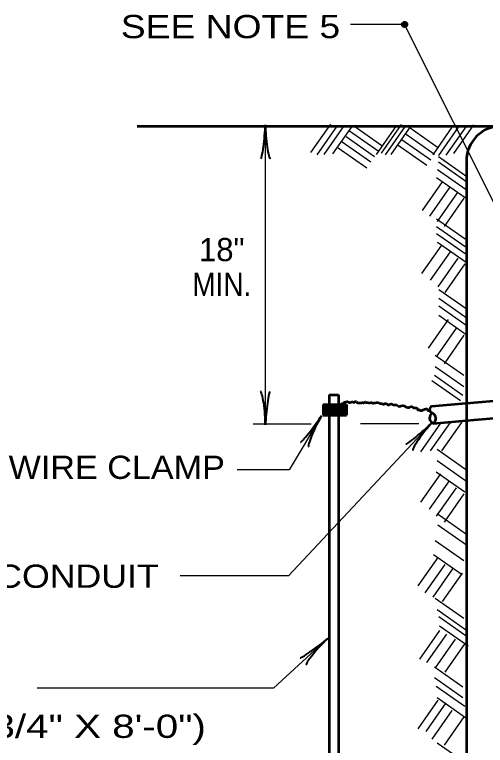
# Model space of a CAD drawing. Extents: x -560 to 120, y 26 to 466.
# Drawn here: x -192.3 to -151.7, y 113.4 to 176.3 of the extents above; entities that cross this region are included whole.
import ezdxf
from ezdxf.enums import TextEntityAlignment as Align

# ---------------------------------------------------------------- set-up
doc = ezdxf.new("R2010")
doc.units = 0
doc.header["$LTSCALE"] = 0.8
doc.header["$PDMODE"] = 32
doc.header["$PDSIZE"] = 0.4
doc.linetypes.add('LONG_DASHED', pattern=[7.5, 6, -1.5])
doc.layers.add('1', color=7, linetype='Continuous', lineweight=53)

msp = doc.modelspace()

# ---------------------------------------------------------------- linework, layer by layer
at = {"layer": '1', "lineweight": 25}
for p, q in [((-158.6532, 175.4604), (-163.3054, 175.4604)), ((-147.0989, 152.3519), (-158.6532, 175.4604)), ((-166.7455, 164.4171), (-165.0248, 166.8745)), ((-160.6313, 164.3796), (-158.9107, 166.837)), ((-170.6512, 140.9738), (-170.6512, 166.7859)), ((-166.1829, 164.2296), (-164.4622, 166.687)), ((-165.5828, 164.2671), (-163.8621, 166.7245)), ((-164.8326, 164.3047), (-163.1119, 166.7621)), ((-163.3972, 166.2917), (-160.9398, 164.571)), ((-163.0597, 166.7417), (-160.6022, 165.0211)), ((-161.0815, 164.2671), (-159.3608, 166.7245)), ((-160.2937, 164.2296), (-158.5731, 166.687)), ((-159.8061, 164.2671), (-158.0854, 166.7245)), ((-158.1832, 166.5542), (-155.7258, 164.8335)), ((-156.2052, 164.2296), (-154.4845, 166.687)), ((-155.7175, 164.1545), (-153.9968, 166.6119)), ((-155.0798, 164.1921), (-153.3592, 166.6495)), ((-154.4047, 164.3421), (-152.684, 166.7995)), ((-163.6973, 165.804), (-161.2398, 164.0833)), ((-158.5208, 165.9915), (-156.0633, 164.2708)), ((-164.0349, 165.3539), (-161.5774, 163.6333)), ((-159.196, 165.0538), (-156.7385, 163.3331)), ((-158.8584, 165.5039), (-156.4009, 163.7832)), ((-164.3725, 164.8287), (-161.915, 163.1081)), ((-155.7451, 164.0785), (-153.2876, 162.3578)), ((-155.7451, 163.6284), (-153.2876, 161.9077)), ((-155.8201, 162.9532), (-153.3626, 161.2325)), ((-157.1053, 159.4282), (-155.3847, 161.8857)), ((-155.8951, 162.278), (-153.4376, 160.5573)), ((-156.4677, 158.9407), (-154.747, 161.3981)), ((-155.83, 158.4905), (-154.1093, 160.9479)), ((-155.2298, 158.0404), (-153.5092, 160.4978)), ((-155.8951, 158.7146), (-153.4376, 156.9939)), ((-155.8951, 158.0394), (-153.4376, 156.3187)), ((-155.8951, 157.4392), (-153.4376, 155.7186)), ((-157.1804, 153.9892), (-155.4597, 156.4467)), ((-155.8201, 156.689), (-153.3626, 154.9683)), ((-156.4302, 153.4266), (-154.7095, 155.884)), ((-155.755, 152.8639), (-154.0343, 155.3213)), ((-155.1548, 152.3762), (-153.4342, 154.8337)), ((-155.7076, 152.6379), (-153.2501, 150.9172)), ((-155.7076, 151.8877), (-153.2501, 150.167)), ((-155.7076, 151.2125), (-153.2501, 149.4918)), ((-156.5803, 147.5749), (-154.8596, 150.0323)), ((-155.7076, 150.4247), (-153.2501, 148.7041)), ((-155.9051, 146.8247), (-154.1844, 149.2822)), ((-155.2298, 146.2246), (-153.5092, 148.682)), ((-156.0077, 146.9738), (-153.5502, 145.2532)), ((-156.0077, 145.9986), (-153.5502, 144.2779)), ((-156.3077, 144.7982), (-153.8502, 143.0776)), ((-156.0827, 145.2484), (-153.6252, 143.5277)), ((-171.7057, 141.0415), (-166.7057, 141.0415)), ((-162.4412, 141.079), (-157.4412, 141.079)), ((-157.2554, 138.6475), (-155.5348, 141.1049)), ((-156.4302, 138.7225), (-154.7095, 141.1799)), ((-155.4549, 138.7225), (-153.7343, 141.1799)), ((-155.8576, 138.8716), (-153.4001, 137.1509)), ((-155.8576, 137.8963), (-153.4001, 136.1757)), ((-157.2554, 134.2962), (-155.5348, 136.7537)), ((-155.9327, 136.9211), (-153.4752, 135.2004)), ((-156.5052, 133.6961), (-154.7845, 136.1535)), ((-155.905, 133.0959), (-154.1843, 135.5533)), ((-155.2298, 132.5708), (-153.5092, 135.0282)), ((-155.8577, 133.32), (-153.4002, 131.5993)), ((-155.7826, 132.3448), (-153.3251, 130.6241)), ((-156.0077, 130.9943), (-153.5502, 129.2737)), ((-156.1577, 129.794), (-153.7002, 128.0733)), ((-157.4805, 127.0943), (-155.7598, 129.5517)), ((-156.8803, 126.4941), (-155.1597, 128.9515)), ((-156.2052, 126.119), (-154.4845, 128.5764)), ((-155.3799, 125.7439), (-153.6592, 128.2013)), ((-156.0077, 126.0431), (-153.5502, 124.3224)), ((-155.8576, 125.0677), (-153.4001, 123.3471)), ((-155.7076, 124.4676), (-153.2501, 122.7469)), ((-155.6325, 123.6424), (-153.175, 121.9218)), ((-157.3305, 120.7926), (-155.6098, 123.25)), ((-156.7303, 120.4925), (-155.0097, 122.9499)), ((-155.9801, 120.0423), (-154.2594, 122.4997)), ((-155.1549, 119.6672), (-153.4342, 122.1247)), ((-156.0828, 120.1163), (-153.6252, 118.3957)), ((-156.0828, 119.2161), (-153.6252, 117.4954)), ((-155.9327, 118.4659), (-153.4752, 116.7452)), ((-157.4805, 114.7909), (-155.7598, 117.2483)), ((-155.8577, 117.4906), (-153.4002, 115.7699)), ((-156.8053, 114.5658), (-155.0847, 117.0232)), ((-156.2802, 113.8907), (-154.5595, 116.3481)), ((-155.2299, 113.3655), (-153.5093, 115.8229)), ((-155.8577, 113.5896), (-153.4002, 111.8689))]:
    msp.add_line(p, q, dxfattribs=at)
at = {"layer": '1'}
for p, q in [((-181.6935, 166.6995), (-147.5832, 166.6995)), ((-165.1448, 143.5618), (-164.3448, 143.5618)), ((-165.1448, 143.5618), (-165.1448, 142.791)), ((-164.3448, 143.543), (-164.3448, 143.2187)), ((-164.3448, 143.543), (-164.3448, 142.791)), ((-165.6699, 142.7062), (-163.6699, 142.7062)), ((-165.6699, 142.7062), (-165.6699, 141.8061)), ((-165.6325, 142.7062), (-165.6325, 141.8061)), ((-165.6232, 142.7062), (-165.6232, 141.8061)), ((-165.6044, 142.7062), (-165.6044, 141.8061)), ((-165.5857, 142.7062), (-165.5857, 141.8061)), ((-165.5575, 142.7062), (-165.5575, 141.8061)), ((-165.5107, 142.7062), (-165.5107, 141.8061)), ((-165.4638, 142.7062), (-165.4638, 141.8061)), ((-165.4169, 142.7062), (-165.4169, 141.8061)), ((-165.3981, 142.7062), (-165.3981, 141.8061)), ((-165.3606, 142.7062), (-165.3606, 141.8061)), ((-165.3512, 142.7062), (-165.3512, 141.8061)), ((-165.3231, 142.7062), (-165.3231, 141.8061)), ((-165.295, 142.7062), (-165.295, 141.8061)), ((-165.295, 142.7062), (-165.295, 141.8061)), ((-165.2856, 142.7062), (-165.2856, 141.8061)), ((-165.2763, 142.7062), (-165.2763, 141.8061)), ((-165.2481, 142.7062), (-165.2481, 141.8061)), ((-165.2293, 142.7062), (-165.2293, 141.8061)), ((-165.22, 142.7062), (-165.22, 141.8061)), ((-165.1918, 142.7062), (-165.1918, 141.8061)), ((-165.1918, 142.7062), (-165.1918, 141.8061)), ((-165.1825, 142.7062), (-165.1825, 141.8061)), ((-165.1543, 142.7062), (-165.1543, 141.8061)), ((-165.1448, 142.8247), (-165.1448, 140.4947)), ((-165.1262, 142.7062), (-165.1262, 141.8061)), ((-165.1262, 142.7062), (-165.1262, 141.8061)), ((-165.0888, 142.7062), (-165.0888, 141.8061)), ((-165.0888, 142.7062), (-165.0888, 141.8061)), ((-165.0699, 142.7062), (-165.0699, 141.8061)), ((-165.0698, 142.7056), (-165.0698, 142.3453)), ((-165.0324, 142.7062), (-165.0324, 141.8061)), ((-165.0324, 142.7062), (-165.0324, 141.8061)), ((-165.0043, 142.7062), (-165.0043, 141.8061)), ((-164.9856, 142.7062), (-164.9856, 141.8061)), ((-164.9668, 142.7062), (-164.9668, 141.8061)), ((-164.9387, 142.7062), (-164.9387, 141.8061)), ((-164.9199, 142.7062), (-164.9199, 141.8061)), ((-164.8918, 142.7062), (-164.8918, 141.8061)), ((-164.8637, 142.7062), (-164.8637, 141.8061)), ((-164.8543, 142.7062), (-164.8543, 141.8061)), ((-164.8449, 142.7062), (-164.8449, 141.8061)), ((-164.8262, 142.7062), (-164.8262, 141.8061)), ((-164.8074, 142.7062), (-164.8074, 141.8061)), ((-164.7981, 142.7062), (-164.7981, 141.8061)), ((-164.7793, 142.7062), (-164.7793, 141.8061)), ((-164.7699, 142.7062), (-164.7699, 141.8061)), ((-164.7606, 142.7062), (-164.7606, 141.8061)), ((-164.7417, 142.7062), (-164.7417, 141.8061)), ((-164.7417, 142.7062), (-164.7417, 141.8061)), ((-164.7417, 142.7062), (-164.7417, 141.8061)), ((-164.7137, 142.7062), (-164.7137, 141.8061)), ((-164.7137, 142.7062), (-164.7137, 141.8061)), ((-164.6855, 142.7062), (-164.6855, 141.8061)), ((-164.6855, 142.7062), (-164.6855, 141.8061)), ((-164.6762, 142.7062), (-164.6762, 141.8061)), ((-164.6574, 142.7062), (-164.6574, 141.8061)), ((-164.6199, 142.7062), (-164.6199, 141.8061)), ((-164.6105, 142.7062), (-164.6105, 141.8061)), ((-164.6105, 142.7062), (-164.6105, 141.8061)), ((-164.5917, 142.7062), (-164.5917, 141.8061)), ((-164.5637, 142.7062), (-164.5637, 141.8061)), ((-164.5542, 142.7062), (-164.5542, 141.8061)), ((-164.5449, 142.7062), (-164.5449, 141.8061)), ((-164.5355, 142.7062), (-164.5355, 141.8061)), ((-164.5262, 142.7062), (-164.5262, 141.8061)), ((-164.498, 142.7062), (-164.498, 141.8061)), ((-164.4793, 142.7062), (-164.4793, 141.8061)), ((-164.4699, 142.7062), (-164.4699, 141.8061)), ((-164.4512, 142.7062), (-164.4512, 141.8061)), ((-164.423, 142.7062), (-164.423, 141.8061)), ((-164.4042, 142.7062), (-164.4042, 141.8061)), ((-164.4042, 142.7062), (-164.4042, 141.8061)), ((-164.3948, 142.7062), (-164.3948, 141.8061)), ((-164.3855, 142.7062), (-164.3855, 141.8061)), ((-164.3667, 142.7062), (-164.3667, 141.8061)), ((-164.3667, 142.7062), (-164.3667, 141.8061)), ((-164.3573, 142.7062), (-164.3573, 141.8061)), ((-164.3448, 142.8342), (-164.3448, 140.5323)), ((-164.3386, 142.7062), (-164.3386, 141.8061)), ((-164.3386, 142.7062), (-164.3386, 141.8061)), ((-164.3293, 142.7062), (-164.3293, 141.8061)), ((-164.3105, 142.7062), (-164.3105, 141.8061)), ((-164.2918, 142.7062), (-164.2918, 141.8061)), ((-164.2823, 142.7062), (-164.2823, 141.8061)), ((-164.2698, 142.7051), (-164.2698, 142.3453)), ((-164.2636, 142.7062), (-164.2636, 141.8061)), ((-164.2542, 142.7062), (-164.2542, 141.8061)), ((-164.2448, 142.7062), (-164.2448, 141.8061)), ((-164.2167, 142.7062), (-164.2167, 141.8061)), ((-164.1886, 142.7062), (-164.1886, 141.8061)), ((-164.1792, 142.7062), (-164.1792, 141.8061)), ((-164.1698, 142.7062), (-164.1698, 141.8061)), ((-164.1511, 142.7062), (-164.1511, 141.8061)), ((-164.1418, 142.7062), (-164.1418, 141.8061)), ((-164.1323, 142.7062), (-164.1323, 141.8061)), ((-164.1043, 142.7062), (-164.1043, 141.8061)), ((-164.0667, 142.7062), (-164.0667, 141.8061)), ((-164.0573, 142.7062), (-164.0573, 141.8061)), ((-164.0573, 142.7062), (-164.0573, 141.8061)), ((-164.0573, 142.7062), (-164.0573, 141.8061)), ((-164.0479, 142.7062), (-164.0479, 141.8061)), ((-164.0198, 142.7062), (-164.0198, 141.8061)), ((-164.0198, 142.7062), (-164.0198, 141.8061)), ((-164.0104, 142.7062), (-164.0104, 141.8061)), ((-164.0011, 142.7062), (-164.0011, 141.8061)), ((-163.9823, 142.7062), (-163.9823, 141.8061)), ((-163.9729, 142.7062), (-163.9729, 141.8061)), ((-163.9636, 142.7062), (-163.9636, 141.8061)), ((-163.9448, 142.7062), (-163.9448, 141.8061)), ((-163.9261, 142.7062), (-163.9261, 141.8061)), ((-163.9167, 142.7062), (-163.9167, 141.8061)), ((-163.9073, 142.7062), (-163.9073, 141.8061)), ((-163.9073, 142.7062), (-163.9073, 141.8061)), ((-163.8792, 142.7062), (-163.8792, 141.8061)), ((-163.8604, 142.7062), (-163.8604, 141.8061)), ((-163.8604, 142.7062), (-163.8604, 141.8061)), ((-163.8511, 142.7062), (-163.8511, 141.8061)), ((-163.8511, 142.7062), (-163.8511, 141.8061)), ((-163.8229, 142.7062), (-163.8229, 141.8061)), ((-163.8136, 142.7062), (-163.8136, 141.8061)), ((-163.8136, 142.7062), (-163.8136, 141.8061)), ((-163.7948, 142.7062), (-163.7948, 141.8061)), ((-163.7948, 142.7062), (-163.7948, 141.8061)), ((-163.7948, 142.7062), (-163.7948, 141.8061)), ((-163.7854, 142.7062), (-163.7854, 141.8061)), ((-163.7854, 142.7062), (-163.7854, 141.8061)), ((-163.7479, 142.7062), (-163.7479, 141.8061)), ((-163.7385, 142.7062), (-163.7385, 141.8061)), ((-163.7292, 142.7062), (-163.7292, 141.8061)), ((-163.7104, 142.7062), (-163.7104, 141.8061)), ((-163.7104, 142.7062), (-163.7104, 141.8061)), ((-163.701, 142.7062), (-163.701, 141.8061)), ((-163.701, 142.7062), (-163.701, 141.8061)), ((-163.6729, 142.7062), (-163.6729, 141.8061)), ((-163.6699, 142.7062), (-163.6699, 141.8061)), ((-156.3286, 142.5751), (-153.34, 142.8366)), ((-165.6699, 141.8061), (-163.6699, 141.8061)), ((-156.1978, 141.0808), (-153.3261, 141.3321)), ((-165.1448, 140.7231), (-165.1448, 83.0187)), ((-164.3448, 140.7231), (-164.3448, 83.0187))]:
    msp.add_line(p, q, dxfattribs=at)
at = {"layer": '1', "linetype": 'LONG_DASHED'}
for p, q in [((-153.3254, 142.8416), (-143.2353, 143.7244)), ((-153.3254, 141.3358), (-142.6482, 142.27))]:
    msp.add_line(p, q, dxfattribs=at)
at = {"layer": '1'}
msp.add_lwpolyline([(-153.3254, 163.6995), (-153.3254, 93.7352), (-116.1271, 93.7352)], dxfattribs=at)
at = {"layer": '1', "lineweight": 25}
for points in [[(-165.8134, 141.7572), (-168.5892, 137.1059), (-173.096, 137.1059)], [(-156.2858, 141.157), (-168.6642, 127.9534), (-177.9922, 127.9534)], [(-165.2883, 122.5519), (-169.9395, 118.2757), (-190.3148, 118.2757)]]:
    msp.add_lwpolyline(points, dxfattribs=at)
at = {"layer": '1'}
for centre, radius, start, end in [((-150.3254, 163.6995), 3, 90, 180), ((-155.9689, 141.5592), 0.5304, 124.39884, 244.42408)]:
    msp.add_arc(centre, radius, start, end, dxfattribs=at)
at = {"layer": '1', "lineweight": 25}
msp.add_arc((-150.3254, 163.6995), 3, 90, 180, dxfattribs=at)
at = {"layer": '1', "lineweight": 40}
for centre, major_axis, ratio, start_param, end_param in [((-170.8628, 165.6654), (-0.1757, -1.7565), 0.07063, 6.2823074, 8.5597026), ((-170.3749, 165.6947), (-0.1562, 1.7857), 0.122415, 0.8963533, 3.1415927), ((-170.9275, 142.065), (0.1562, -1.7857), 0.122415, 0.8963533, 3.1415927), ((-170.4396, 142.0943), (0.1757, 1.7565), 0.07063, 6.2823074, 8.5597026), ((-166.5693, 140.9034), (1.0509, 1.4183), 0.07063, 3.1407148, 5.41811), ((-166.1353, 140.6785), (0.781, 1.6134), 0.122415, 0.8963533, 3.1415927), ((-157.2065, 140.4843), (-1.3295, -1.1613), 0.07063, 6.2823074, 8.5597026), ((-156.8305, 140.172), (1.1074, 1.4095), 0.122415, 0.8963533, 3.1415927), ((-166.2563, 121.9493), (-1.4119, -1.0595), 0.07063, 6.2823074, 8.5597026), ((-165.9045, 121.61), (1.2089, 1.3235), 0.122415, 0.8963533, 3.1415927)]:
    msp.add_ellipse(centre, major_axis=major_axis, ratio=ratio, start_param=start_param, end_param=end_param, dxfattribs=at)
at = {"layer": '1'}
for centre, major_axis, ratio, start_param, end_param in [((-156.1629, 142.3125), (0.2967, 0.1873), 0.884789, 1.5707963, 3.8873113), ((-156.4965, 141.5188), (0.483, -0.2191), 0.984898, 5.7525138, 7.8539045)]:
    msp.add_ellipse(centre, major_axis=major_axis, ratio=ratio, start_param=start_param, end_param=end_param, dxfattribs=at)
msp.add_spline([(-164.1994, 142.7178), (-163.9182, 142.8491), (-163.5242, 142.9617), (-163.4305, 142.8866), (-163.1304, 142.9617), (-162.9992, 142.9053), (-162.8866, 142.9804), (-162.6803, 142.8491), (-162.549, 142.8678), (-162.399, 142.8678), (-162.2489, 142.8866), (-162.1927, 142.8678), (-162.0614, 142.9429), (-161.9864, 142.9053), (-161.7988, 142.8866), (-161.6488, 142.8678), (-161.48, 142.8866), (-161.4237, 142.8303), (-161.2737, 142.8491), (-161.0862, 142.8866), (-160.8423, 142.8491), (-160.7673, 142.8116), (-160.5985, 142.7928), (-160.5048, 142.7553), (-160.2609, 142.8116), (-160.0171, 142.6803), (-159.9046, 142.7553), (-159.5482, 142.6803), (-159.3419, 142.6991), (-159.1919, 142.5677), (-158.9481, 142.6053), (-158.7043, 142.6053), (-158.4792, 142.4928), (-158.2729, 142.474), (-158.1792, 142.5115), (-157.9728, 142.5115), (-157.8603, 142.4365), (-157.7852, 142.4365), (-157.5415, 142.324), (-157.4852, 142.2302), (-157.4852, 142.2489), (-157.2602, 142.1927), (-157.1101, 142.2302), (-156.8287, 142.3427), (-156.7163, 142.324), (-156.6788, 142.2489), (-156.6412, 142.2114), (-156.5662, 142.2114), (-156.3974, 142.1739)], degree=3, dxfattribs=at)
msp.add_point((-158.6532, 175.4604), dxfattribs=at)

# ---------------------------------------------------------------- texts
for s, width, p in [('SEE NOTE 5', 1.2, (-183.1122, 174.2734)), ('GROUND WIRE CLAMP', 1.1, (-206.6709, 136.3096)), ('1/2" CONDUIT', 1.15, (-200.0684, 126.9312)), ('GROUND ROD (3/4" X 8\'-0")', 1.3, (-220.4383, 114.0019))]:
    msp.add_text(s, height=2, dxfattribs=dict(at, width=width)).set_placement(p)
msp.add_text('18"', height=2, dxfattribs=at).set_placement((-174.409, 155.0658), align=Align.CENTER)
at = {"layer": '1', "width": 0.9}
msp.add_text('MIN.', height=2, dxfattribs=at).set_placement((-174.409, 152.0658), align=Align.CENTER)

doc.saveas('drawing.dxf')
